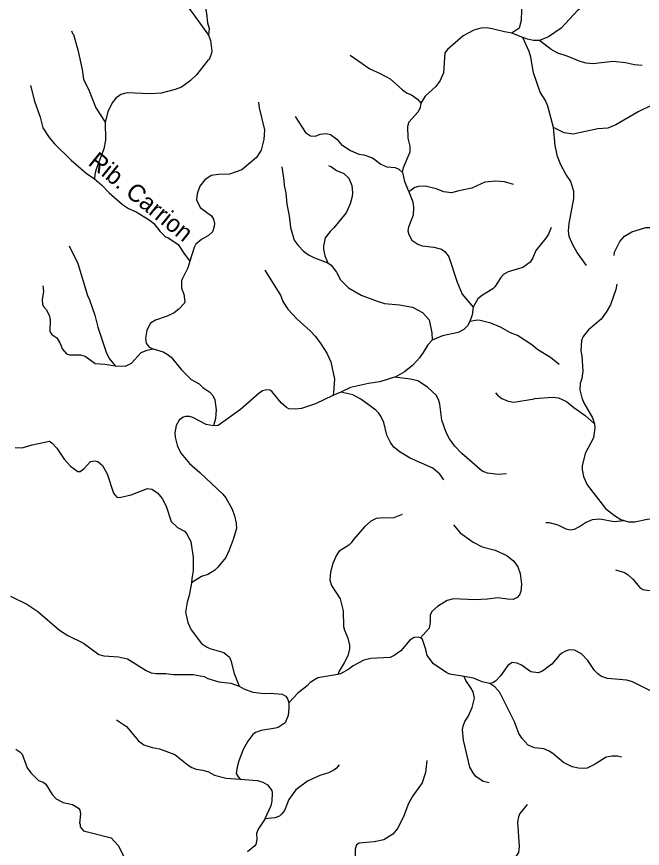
# Model space of a CAD drawing. Extents: x 500 to 555.2, y 9115.7 to 9171.
# Drawn here: x 528.19 to 533.92, y 9135.74 to 9143.36 of the extents above; entities that cross this region are included whole.
import ezdxf
from ezdxf.enums import TextEntityAlignment as Align

# ---------------------------------------------------------------- set-up
doc = ezdxf.new("R2010")
doc.units = 0
doc.header["$LTSCALE"] = 0.064
doc.layers.add('61', color=7, linetype='Continuous')
doc.layers.add('7', color=7, linetype='Continuous', lineweight=25)

msp = doc.modelspace()

# ---------------------------------------------------------------- linework, layer by layer
at = {"layer": '7'}
for p, q in [((532.8274, 9143.166), (532.7257, 9143.206)), ((531.1589, 9139.9191), (531.0875, 9139.8862)), ((529.994, 9139.6086), (529.9264, 9139.6229))]:
    msp.add_line(p, q, dxfattribs=at)
for points in [[(534.4742, 9144.2769), (534.4899, 9144.1646), (534.4965, 9144.0334), (534.4933, 9143.901), (534.47, 9143.7899), (534.4343, 9143.7344), (534.3943, 9143.7005), (534.3525, 9143.6763), (534.285, 9143.654), (534.2036, 9143.6426), (534.033, 9143.6473), (533.892, 9143.6442), (533.8193, 9143.6342), (533.7832, 9143.6211), (533.6414, 9143.5438), (533.5779, 9143.5183), (533.4747, 9143.4899), (533.4053, 9143.4646), (533.3305, 9143.4144), (533.1782, 9143.2495), (533.0607, 9143.1715), (532.98, 9143.1378)], [(529.6091, 9143.9899), (529.673, 9143.9438), (529.7397, 9143.8835), (529.7731, 9143.8379), (529.7821, 9143.8357), (529.8267, 9143.7671), (529.8362, 9143.7299), (529.8367, 9143.6871), (529.8482, 9143.6287), (529.907, 9143.5014), (529.9293, 9143.3848), (529.9386, 9143.3001), (529.953, 9143.2461), (529.9483, 9143.1857)], [(529.0863, 9143.8755), (529.1033, 9143.8572), (529.1147, 9143.8539), (529.3079, 9143.7173), (529.6741, 9143.5276), (529.7315, 9143.48), (529.7906, 9143.4062), (529.9483, 9143.1857)], [(532.8407, 9143.7046), (532.8388, 9143.7026), (532.8215, 9143.6515), (532.8072, 9143.5079), (532.8138, 9143.4193), (532.8119, 9143.321), (532.7918, 9143.2518), (532.7257, 9143.206)], [(528.6933, 9143.2275), (528.7016, 9143.2013), (528.7112, 9143.1911), (528.751, 9143.0507), (528.7898, 9142.8728), (528.803, 9142.7823), (528.8556, 9142.6779), (528.9151, 9142.52), (529.0012, 9142.3893)], [(532.7257, 9143.206), (532.6581, 9143.2167), (532.558, 9143.2425), (532.4978, 9143.2522), (532.442, 9143.2505), (532.3784, 9143.2337), (532.2812, 9143.1802), (532.1367, 9143.0557), (532.1137, 9143.0261), (532.0987, 9142.8402), (532.0703, 9142.7726), (532.0284, 9142.7178), (531.9313, 9142.627), (531.893, 9142.563)], [(529.9483, 9143.1857), (529.9486, 9143.1853), (529.9676, 9143.138), (529.9775, 9143.0407), (529.9739, 9143.0112), (529.9557, 9142.9631), (529.9404, 9142.9506), (529.8378, 9142.8219), (529.7797, 9142.7672), (529.7007, 9142.7118), (529.643, 9142.6894), (529.5145, 9142.6566), (529.4151, 9142.6486), (529.2028, 9142.6597), (529.1451, 9142.642), (529.0996, 9142.6112), (529.0657, 9142.5664), (529.0267, 9142.4852), (529.0012, 9142.3893)], [(533.1083, 9142.3399), (533.1081, 9142.3422), (533.055, 9142.5363), (533.0353, 9142.5888), (532.9857, 9142.6655), (532.9239, 9142.8404), (532.8995, 9142.9839), (532.8858, 9143.0355), (532.8274, 9143.166)], [(532.98, 9143.1378), (532.9781, 9143.137), (532.925, 9143.1382), (532.8691, 9143.1496), (532.8274, 9143.166)], [(533.9193, 9142.9099), (533.8482, 9142.9143), (533.7655, 9142.9323), (533.6532, 9142.9452), (533.4671, 9142.9225), (533.4053, 9142.9291), (533.3506, 9142.9458), (533.2341, 9142.9943), (533.1468, 9143.0208), (533.0869, 9143.0562), (532.98, 9143.1378)], [(531.2464, 9143.0027), (531.4259, 9142.8775), (531.5206, 9142.8365), (531.6113, 9142.7861), (531.7241, 9142.6872), (531.7683, 9142.657), (531.8062, 9142.6394), (531.8611, 9142.6002), (531.893, 9142.563)], [(528.3195, 9142.7268), (528.356, 9142.5809), (528.4055, 9142.4372), (528.4325, 9142.3369), (528.4879, 9142.2488), (528.5384, 9142.1914), (528.6897, 9142.0415), (528.8273, 9141.9239), (528.9056, 9141.8726)], [(530.4068, 9142.572), (530.4128, 9142.5198), (530.4615, 9142.3204), (530.4563, 9142.2306), (530.4302, 9142.1336), (530.3873, 9142.0674), (530.2533, 9141.9522), (530.14, 9141.9149), (530.0406, 9141.9119), (529.9738, 9141.9017), (529.9137, 9141.861), (529.8679, 9141.805), (529.8433, 9141.7338), (529.8388, 9141.6804), (529.8727, 9141.6087), (529.9742, 9141.533), (529.9937, 9141.5007), (530.0021, 9141.4627), (529.9987, 9141.434), (529.9833, 9141.3857), (529.948, 9141.3527), (529.8826, 9141.3165), (529.833, 9141.2716), (529.8183, 9141.2421), (529.776, 9141.1162)], [(531.893, 9142.563), (531.8917, 9142.5609), (531.8866, 9142.5235), (531.8692, 9142.4851), (531.7818, 9142.3902), (531.7691, 9142.3506), (531.7735, 9142.2432), (531.7917, 9142.1695), (531.7933, 9142.116), (531.7295, 9141.971), (531.7231, 9141.9323), (531.7236, 9141.9301)], [(534.0073, 9142.547), (533.8838, 9142.4855), (533.6785, 9142.3649), (533.6038, 9142.3354), (533.5134, 9142.3284), (533.287, 9142.2811), (533.2063, 9142.2924), (533.1083, 9142.3399)], [(529.0012, 9142.3893), (529.0047, 9142.2246), (528.9882, 9142.1459), (528.9152, 9141.9513), (528.9066, 9141.9103), (528.9056, 9141.8726)], [(530.7413, 9142.4414), (530.8373, 9142.2957), (530.881, 9142.2645), (530.9284, 9142.2629), (530.9697, 9142.2795), (531.0268, 9142.2874), (531.0662, 9142.2779), (531.123, 9142.233), (531.1701, 9142.1781), (531.1785, 9142.1771), (531.2494, 9142.1298), (531.3247, 9142.0977), (531.3719, 9142.0907), (531.4506, 9142.0628), (531.5261, 9142.005), (531.5799, 9141.9809), (531.6579, 9141.9764), (531.6914, 9141.9589), (531.7236, 9141.9301)], [(533.4105, 9141.0772), (533.3236, 9141.1957), (533.2878, 9141.2608), (533.2519, 9141.3422), (533.245, 9141.3962), (533.2501, 9141.4635), (533.2942, 9141.6911), (533.2942, 9141.7555), (533.2649, 9141.8458), (533.2192, 9141.9147), (533.174, 9141.9984), (533.1441, 9142.0754), (533.122, 9142.1767), (533.1083, 9142.3399)], [(531.0478, 9141.9925), (531.0745, 9141.9815), (531.1214, 9141.9487), (531.1871, 9141.9191), (531.2327, 9141.8775), (531.2616, 9141.8098), (531.2683, 9141.7437), (531.2652, 9141.711), (531.2468, 9141.6434), (531.2075, 9141.5589), (531.0956, 9141.4228), (531.0619, 9141.3903), (531.0174, 9141.3306), (531.0013, 9141.2555), (531.002, 9141.2264), (531.0143, 9141.1672), (531.0415, 9141.1029)], [(530.6196, 9141.982), (530.6387, 9141.8572), (530.6406, 9141.8106), (530.6551, 9141.7417), (530.665, 9141.6383), (530.6859, 9141.531), (530.6995, 9141.4242), (530.7339, 9141.31), (530.7679, 9141.2612), (530.8175, 9141.2083), (530.8629, 9141.1765), (530.9186, 9141.1478), (531.0415, 9141.1029)], [(531.7236, 9141.9301), (531.7429, 9141.8473), (531.7837, 9141.7516)], [(528.9056, 9141.8726), (528.9682, 9141.8175), (529.0374, 9141.7434), (529.1602, 9141.6352), (529.2168, 9141.6005), (529.2848, 9141.5679), (529.4145, 9141.4891), (529.4466, 9141.462), (529.5032, 9141.3935), (529.5556, 9141.3417), (529.5761, 9141.3341), (529.6708, 9141.2706), (529.7272, 9141.1814), (529.776, 9141.1162)], [(532.7404, 9141.819), (532.6599, 9141.8448), (532.5804, 9141.8511), (532.4795, 9141.8393), (532.3599, 9141.7859), (532.2419, 9141.7627), (532.174, 9141.743), (532.1022, 9141.7524), (532.034, 9141.7809), (531.9361, 9141.8037), (531.8713, 9141.8004), (531.8378, 9141.7922), (531.7837, 9141.7516)], [(531.7837, 9141.7516), (531.8179, 9141.6619), (531.8245, 9141.6085), (531.8212, 9141.5397), (531.7784, 9141.4298), (531.7739, 9141.3953), (531.782, 9141.3625), (531.8095, 9141.3105), (531.8666, 9141.2742), (531.904, 9141.259), (532.0116, 9141.246), (532.083, 9141.228), (532.1149, 9141.2017), (532.1489, 9141.1583), (532.2259, 9140.9243), (532.2718, 9140.8161), (532.3712, 9140.6957)], [(533.6627, 9141.1679), (533.6658, 9141.2013), (533.7145, 9141.2983), (533.7569, 9141.3475), (533.8242, 9141.3869), (533.9543, 9141.4264), (534.0029, 9141.4265), (534.1613, 9141.4446), (534.2637, 9141.4821), (534.3414, 9141.5035), (534.5043, 9141.5199), (534.6085, 9141.5154)], [(533.0854, 9141.4261), (533.0613, 9141.3658), (533.0387, 9141.3268), (532.9451, 9141.216), (532.9173, 9141.1465), (532.895, 9141.1079), (532.8278, 9141.0588), (532.6929, 9141.0198), (532.649, 9140.9942), (532.6238, 9140.9676), (532.5709, 9140.8819), (532.5522, 9140.8631), (532.4572, 9140.8077), (532.4147, 9140.7732), (532.3712, 9140.6957)], [(528.6735, 9141.2564), (528.7509, 9141.0961), (528.8391, 9140.8021), (528.8589, 9140.7621), (528.908, 9140.6226), (528.9344, 9140.5135), (529.0107, 9140.2844), (529.0378, 9140.2274), (529.0941, 9140.1587)], [(529.776, 9141.1162), (529.7581, 9141.0573), (529.7022, 9140.9391), (529.7022, 9140.8688), (529.7235, 9140.814), (529.7301, 9140.7445), (529.7249, 9140.731), (529.6774, 9140.6769), (529.6339, 9140.6432), (529.5702, 9140.6126), (529.462, 9140.578), (529.4157, 9140.5506), (529.3842, 9140.4871), (529.3708, 9140.4137), (529.3768, 9140.3654), (529.4058, 9140.3302), (529.4391, 9140.3154)], [(531.0415, 9141.1029), (531.0715, 9141.0802), (531.1216, 9141.0161), (531.158, 9140.9479), (531.2308, 9140.8727), (531.3476, 9140.8072), (531.5005, 9140.7471), (531.561, 9140.7303), (531.6981, 9140.7176), (531.8174, 9140.6949), (531.9066, 9140.6472), (531.9689, 9140.5793), (531.9945, 9140.4615), (531.9952, 9140.3958)], [(530.4633, 9141.0353), (530.61, 9140.7994), (530.6303, 9140.7496), (530.676, 9140.6789), (530.7587, 9140.5862), (530.8798, 9140.4799), (530.9273, 9140.429), (530.9782, 9140.3619), (531.0323, 9140.2766), (531.0669, 9140.1972), (531.1012, 9140.0371), (531.0943, 9139.9117), (531.0875, 9139.8862)], [(528.4297, 9140.892), (528.4374, 9140.8442), (528.4243, 9140.7648), (528.4273, 9140.7245), (528.4369, 9140.7024), (528.4629, 9140.6738), (528.4902, 9140.6232), (528.498, 9140.5849), (528.4951, 9140.4751), (528.5143, 9140.4475), (528.5581, 9140.4146), (528.5863, 9140.3689), (528.6113, 9140.3127), (528.6464, 9140.2699), (528.6759, 9140.2587), (528.7763, 9140.2585), (528.8193, 9140.2477), (528.911, 9140.1801), (529.0007, 9140.1731), (529.0941, 9140.1587)], [(533.6864, 9140.9057), (533.6779, 9140.8567), (533.6302, 9140.7189), (533.5912, 9140.6506), (533.5428, 9140.5874), (533.4289, 9140.4882), (533.3781, 9140.4272), (533.3647, 9140.3903), (533.3582, 9140.2969), (533.3664, 9140.2497), (533.3762, 9140.1119), (533.3664, 9140.0437), (533.3531, 9139.9963), (533.3485, 9139.9398), (533.3657, 9139.8678), (533.3855, 9139.822), (533.4641, 9139.6823), (533.4818, 9139.6286)], [(532.3712, 9140.6957), (532.3629, 9140.6258), (532.3418, 9140.5655)], [(532.3418, 9140.5655), (532.321, 9140.5256), (532.2872, 9140.4915), (532.235, 9140.4659), (532.091, 9140.4342), (531.9952, 9140.3958)], [(533.1581, 9140.1726), (533.0789, 9140.2343), (532.9652, 9140.3052), (532.9104, 9140.352), (532.7764, 9140.4385), (532.7139, 9140.4618), (532.6217, 9140.5144), (532.5327, 9140.549), (532.4354, 9140.5749), (532.4111, 9140.5767), (532.3418, 9140.5655)], [(531.9952, 9140.3958), (531.9581, 9140.3522), (531.9126, 9140.2813), (531.8803, 9140.234), (531.8167, 9140.1638), (531.743, 9140.1047), (531.6561, 9140.0552), (531.6525, 9140.0541)], [(529.0941, 9140.1587), (529.0986, 9140.158), (529.187, 9140.1555), (529.2437, 9140.1824), (529.3305, 9140.2801), (529.3851, 9140.3042), (529.4391, 9140.3154)], [(529.4391, 9140.3154), (529.4413, 9140.3144), (529.5332, 9140.287), (529.5708, 9140.2667), (529.6057, 9140.2383), (529.7, 9140.1213), (529.7907, 9140.0355), (529.8615, 9139.9936), (529.8962, 9139.9613), (529.9588, 9139.9192), (529.988, 9139.889), (530.0073, 9139.8486), (530.0169, 9139.7565), (530.0111, 9139.6758), (529.994, 9139.6086)], [(531.6525, 9140.0541), (531.5169, 9140.0127), (531.4118, 9139.9988), (531.2487, 9139.9605), (531.1589, 9139.9191)], [(532.6781, 9139.1699), (532.6016, 9139.1646), (532.5038, 9139.1776), (532.4547, 9139.1959), (532.2665, 9139.3573), (532.2046, 9139.4233), (532.1537, 9139.4904), (532.1244, 9139.5478), (532.084, 9139.6609), (532.0676, 9139.8093), (532.0585, 9139.8417), (532.0361, 9139.8862), (531.9529, 9139.9642), (531.8666, 9140.0208), (531.7979, 9140.0381), (531.6525, 9140.0541)], [(531.0875, 9139.8862), (530.9283, 9139.8128), (530.7995, 9139.7695), (530.7425, 9139.7622), (530.685, 9139.7655), (530.6622, 9139.7785), (530.6148, 9139.8198), (530.5302, 9139.9222), (530.5116, 9139.9369), (530.4795, 9139.9385), (530.4436, 9139.9303), (530.4136, 9139.9106), (530.2423, 9139.7585), (530.0375, 9139.6146), (529.994, 9139.6086)], [(532.1021, 9139.1143), (532.0673, 9139.1677), (532.0036, 9139.2222), (531.7953, 9139.3154), (531.7021, 9139.3675), (531.6462, 9139.415), (531.6144, 9139.457), (531.5807, 9139.5242), (531.5525, 9139.6394), (531.5266, 9139.6979), (531.5051, 9139.7282), (531.4797, 9139.7523), (531.3418, 9139.8537), (531.2712, 9139.8937), (531.1589, 9139.9191)], [(532.5759, 9139.9123), (532.5953, 9139.8901), (532.6347, 9139.8616), (532.6913, 9139.8368), (532.7431, 9139.8276), (532.9295, 9139.8566), (532.9368, 9139.8615), (533.0994, 9139.8729), (533.1544, 9139.8661), (533.2266, 9139.834), (533.2941, 9139.7768), (533.398, 9139.7038), (533.4818, 9139.6286)], [(529.9264, 9139.6229), (529.8037, 9139.6877), (529.7736, 9139.6959), (529.7365, 9139.696), (529.7158, 9139.6895), (529.678, 9139.6617), (529.6518, 9139.6119), (529.64, 9139.5445), (529.6433, 9139.5075), (529.6644, 9139.4204), (529.6975, 9139.3575), (529.7747, 9139.2656), (529.8699, 9139.1836), (530.0782, 9138.9835), (530.1062, 9138.9508), (530.1636, 9138.8481), (530.1861, 9138.7866), (530.2008, 9138.7201), (530.2038, 9138.6698), (530.1745, 9138.5681), (530.1377, 9138.4708), (530.1067, 9138.4061), (530.0336, 9138.3153), (530.0022, 9138.2853), (529.9424, 9138.2497), (529.8845, 9138.2319), (529.793, 9138.1717)], [(533.4818, 9139.6286), (533.4874, 9139.5908), (533.4751, 9139.5007), (533.3966, 9139.3562), (533.3711, 9139.2438), (533.3685, 9139.211), (533.3811, 9139.1455), (533.415, 9139.0713), (533.5843, 9138.8532), (533.6651, 9138.7889), (533.7226, 9138.7537), (533.7538, 9138.7445)], [(528.1776, 9139.4132), (528.2428, 9139.409), (528.334, 9139.4367), (528.4489, 9139.4605), (528.491, 9139.4711), (528.5148, 9139.4539), (528.5584, 9139.406), (528.6276, 9139.3045), (528.6831, 9139.2404), (528.7527, 9139.1931), (528.7741, 9139.1928), (528.8109, 9139.2199), (528.8661, 9139.2827), (528.911, 9139.2908), (528.9356, 9139.2832), (528.9772, 9139.2473), (529.0189, 9139.1691), (529.0794, 9138.9931), (529.1089, 9138.9561), (529.1317, 9138.9531), (529.2402, 9138.9793), (529.3898, 9139.0363), (529.4291, 9139.0316), (529.4806, 9138.9971), (529.5245, 9138.9435), (529.5596, 9138.8752), (529.6053, 9138.7354), (529.663, 9138.6808), (529.727, 9138.6453), (529.7464, 9138.6259), (529.787, 9138.5516), (529.8087, 9138.4034), (529.8069, 9138.2853), (529.7958, 9138.2131), (529.793, 9138.1717)], [(531.7214, 9138.7972), (531.6454, 9138.7673), (531.5162, 9138.7658), (531.4835, 9138.7608), (531.4343, 9138.7363), (531.3759, 9138.6862), (531.2753, 9138.569), (531.2554, 9138.5383), (531.2326, 9138.5172), (531.1431, 9138.4581), (531.1209, 9138.4247), (531.0867, 9138.349), (531.0649, 9138.2706), (531.0606, 9138.1985), (531.0732, 9138.1497), (531.1534, 9138.0267), (531.1815, 9137.9178), (531.185, 9137.7729), (531.193, 9137.7381), (531.2247, 9137.6671), (531.2405, 9137.6029), (531.2389, 9137.5695), (531.2226, 9137.5045), (531.1906, 9137.4403), (531.1433, 9137.3645), (531.132, 9137.3344)], [(533.0386, 9138.7245), (533.0674, 9138.7245), (533.1467, 9138.705), (533.2189, 9138.6671), (533.2637, 9138.6594), (533.2988, 9138.6647), (533.3462, 9138.687), (533.4012, 9138.7242), (533.4655, 9138.7527), (533.5308, 9138.7576), (533.6638, 9138.7331), (533.7538, 9138.7445)], [(533.7538, 9138.7445), (533.7944, 9138.7326), (533.8511, 9138.7326), (533.9642, 9138.7561), (534.0667, 9138.7585), (534.1341, 9138.7445), (534.2418, 9138.7005), (534.348, 9138.6459), (534.4158, 9138.6247), (534.478, 9138.6249), (534.5321, 9138.6401)], [(532.1925, 9138.7036), (532.2529, 9138.6295), (532.3709, 9138.546), (532.4548, 9138.5012), (532.5738, 9138.4703), (532.6797, 9138.4244), (532.7428, 9138.3726), (532.7808, 9138.3197), (532.8007, 9138.2582), (532.8137, 9138.1606), (532.8082, 9138.0936), (532.7972, 9138.0642), (532.7746, 9138.038), (532.7392, 9138.0196), (532.685, 9138.0223), (532.5987, 9138.036), (532.5031, 9138.0228), (532.3871, 9138.018), (532.1914, 9138.0259), (532.1325, 9138.011), (532.0439, 9137.9568), (531.9933, 9137.9106), (531.9788, 9137.8779), (531.977, 9137.8113), (531.9686, 9137.7567), (531.8898, 9137.6698)], [(533.6766, 9138.2922), (533.7562, 9138.2674), (533.7923, 9138.2445), (533.8332, 9138.2055), (533.8985, 9138.1289), (533.9262, 9138.1103), (533.9799, 9138.1033), (534.032, 9138.1157), (534.0805, 9138.1385), (534.1641, 9138.1987), (534.1976, 9138.2594), (534.2179, 9138.318), (534.2569, 9138.3667), (534.3184, 9138.4017), (534.4437, 9138.4384), (534.4803, 9138.4608), (534.4969, 9138.4794), (534.5162, 9138.5166), (534.5321, 9138.6401)], [(529.793, 9138.1717), (529.7715, 9138.0582), (529.7528, 9137.996), (529.7384, 9137.9042), (529.7575, 9137.8111), (529.7886, 9137.7417), (529.8844, 9137.6176), (529.9285, 9137.5865), (529.9598, 9137.5724), (530.0882, 9137.5349), (530.1394, 9137.4917), (530.1533, 9137.4612), (530.1846, 9137.3431), (530.2293, 9137.2264)], [(528.134, 9138.0509), (528.2843, 9137.9771), (528.3842, 9137.9103), (528.5839, 9137.7387), (528.6611, 9137.6905), (528.8031, 9137.6209), (528.9447, 9137.5157), (528.9889, 9137.5046), (529.1253, 9137.4945), (529.2072, 9137.4785), (529.3768, 9137.3703), (529.4221, 9137.3501), (529.4679, 9137.3422), (529.5563, 9137.3435), (529.6266, 9137.3339), (529.8077, 9137.3337), (529.908, 9137.3143), (529.943, 9137.2957), (530.0433, 9137.2667), (530.1521, 9137.2549), (530.2293, 9137.2264)], [(531.8898, 9137.6698), (531.8894, 9137.6702), (531.8668, 9137.6758), (531.8305, 9137.6713), (531.7932, 9137.6465), (531.7081, 9137.5505), (531.648, 9137.5065), (531.6128, 9137.4904), (531.4349, 9137.4799), (531.3701, 9137.4655), (531.2716, 9137.4134), (531.2331, 9137.3835), (531.1575, 9137.3386), (531.132, 9137.3344)], [(532.289, 9137.3146), (532.1586, 9137.3374), (532.1292, 9137.349), (532.0088, 9137.4302), (531.9496, 9137.5089), (531.939, 9137.5616), (531.9074, 9137.654), (531.8898, 9137.6698)], [(534.0455, 9137.1583), (533.8321, 9137.2661), (533.7792, 9137.2815), (533.6034, 9137.296), (533.5458, 9137.3156), (533.512, 9137.3393), (533.4823, 9137.3689), (533.421, 9137.4613), (533.3653, 9137.522), (533.2994, 9137.5556), (533.255, 9137.56), (533.2185, 9137.5484), (533.1829, 9137.529), (533.1593, 9137.5089), (533.093, 9137.428), (533.0062, 9137.3654), (532.9656, 9137.3503), (532.8995, 9137.3585), (532.8131, 9137.4178), (532.7745, 9137.436), (532.7289, 9137.4448), (532.6896, 9137.4163), (532.6234, 9137.3208), (532.5775, 9137.273), (532.5505, 9137.2574), (532.5234, 9137.2504)], [(531.132, 9137.3344), (530.9482, 9137.3039), (530.8804, 9137.2605), (530.8519, 9137.2306), (530.7651, 9137.1633), (530.684, 9137.0754)], [(532.5174, 9136.343), (532.4642, 9136.355), (532.3971, 9136.4006), (532.3712, 9136.4329), (532.3403, 9136.4864), (532.2839, 9136.7309), (532.2741, 9136.8287), (532.2791, 9136.8615), (532.2953, 9136.9019), (532.3252, 9136.949), (532.3616, 9137.0322), (532.3853, 9137.1172), (532.3708, 9137.1748), (532.3511, 9137.2125), (532.3047, 9137.2775), (532.289, 9137.3146)], [(532.5234, 9137.2504), (532.5225, 9137.2509), (532.4529, 9137.2669), (532.375, 9137.2995), (532.289, 9137.3146)], [(530.2293, 9137.2264), (530.2716, 9137.2024), (530.355, 9137.1732), (530.4593, 9137.1601), (530.5138, 9137.1617), (530.6212, 9137.1537), (530.6551, 9137.1362), (530.6758, 9137.1052), (530.684, 9137.0754)], [(533.7295, 9136.5783), (533.6925, 9136.5856), (533.6444, 9136.586), (533.5902, 9136.5778), (533.4883, 9136.5115), (533.4156, 9136.4773), (533.3751, 9136.4718), (533.3349, 9136.4775), (533.2771, 9136.4887), (533.1982, 9136.5277), (533.1018, 9136.6113), (533.0679, 9136.6318), (533.0175, 9136.6518), (532.9328, 9136.6632), (532.8767, 9136.6858), (532.819, 9136.7472), (532.7901, 9136.7938), (532.7512, 9136.9008), (532.6152, 9137.1698), (532.5709, 9137.2207), (532.5234, 9137.2504)], [(530.684, 9137.0754), (530.6833, 9137.0245), (530.6779, 9136.9584), (530.6491, 9136.8918), (530.5848, 9136.8496), (530.5616, 9136.8419), (530.4304, 9136.8221), (530.3792, 9136.8014), (530.355, 9136.7844), (530.3077, 9136.7243), (530.2666, 9136.6456), (530.2265, 9136.5439), (530.2103, 9136.4861), (530.2026, 9136.4274), (530.2198, 9136.396), (530.2389, 9136.3766), (530.2396, 9136.3765)], [(529.1047, 9136.9185), (529.1961, 9136.8574), (529.3071, 9136.7266), (529.3571, 9136.6895), (529.4318, 9136.665), (529.4982, 9136.6533), (529.6413, 9136.6007), (529.7615, 9136.5048), (529.797, 9136.4826), (529.8363, 9136.4675), (529.895, 9136.458), (529.9492, 9136.4416), (530.0031, 9136.4114), (530.11, 9136.3842), (530.2396, 9136.3765)], [(528.1843, 9136.6492), (528.2214, 9136.6244), (528.2417, 9136.6028), (528.2863, 9136.4783), (528.32, 9136.4335), (528.3903, 9136.3647), (528.4351, 9136.3467), (528.4589, 9136.3281), (528.5174, 9136.2338), (528.5545, 9136.1964), (528.6161, 9136.1633), (528.7015, 9136.1447), (528.7584, 9136.1106), (528.7687, 9136.0904), (528.7751, 9136.0566), (528.7672, 9135.9682), (528.7719, 9135.9653), (528.7744, 9135.9385), (528.8036, 9135.9021), (529.0563, 9135.8397), (529.1201, 9135.7686), (529.1821, 9135.6478), (529.2558, 9135.5426), (529.2768, 9135.4849)], [(531.947, 9136.5478), (531.9359, 9136.4378), (531.9053, 9136.3412), (531.8204, 9136.223), (531.7797, 9136.1515), (531.7372, 9136.0394), (531.6828, 9135.9271), (531.6365, 9135.873), (531.5539, 9135.82), (531.4648, 9135.8019), (531.327, 9135.7898), (531.3024, 9135.7747), (531.29, 9135.7337), (531.2915, 9135.6084), (531.2695, 9135.4791), (531.2436, 9135.4208), (531.2048, 9135.3661), (531.1729, 9135.3324), (531.1171, 9135.2966)], [(531.1436, 9136.5058), (531.121, 9136.4766), (531.0963, 9136.458), (531.0477, 9136.4336), (530.9663, 9136.4076), (530.8536, 9136.3562), (530.7482, 9136.2786), (530.6834, 9136.1896), (530.6432, 9136.09), (530.6202, 9136.057), (530.5971, 9136.0364), (530.5544, 9136.0216), (530.4641, 9136.0116)], [(530.2396, 9136.3765), (530.3979, 9136.3632), (530.4457, 9136.3466), (530.4894, 9136.3234), (530.5279, 9136.2706), (530.532, 9136.2513), (530.5288, 9136.1733), (530.5202, 9136.1326), (530.4641, 9136.0116)], [(532.8661, 9136.1438), (532.8006, 9136.0626), (532.7865, 9136.0304), (532.7793, 9135.9829), (532.7923, 9135.7592), (532.7858, 9135.7051), (532.7468, 9135.6467), (532.6999, 9135.6225), (532.656, 9135.5634), (532.6284, 9135.4935), (532.612, 9135.4246), (532.6071, 9135.3781), (532.6204, 9135.2668), (532.6234, 9135.1557), (532.6085, 9135.0867), (532.5845, 9135.0403)], [(530.4641, 9136.0116), (530.4626, 9136.0083), (530.4019, 9135.9185), (530.3878, 9135.8788), (530.3908, 9135.8216), (530.381, 9135.7779), (530.3724, 9135.764), (530.3046, 9135.7095)]]:
    msp.add_lwpolyline(points, dxfattribs=at)

# ---------------------------------------------------------------- texts
at = {"layer": '61'}
msp.add_text('Rib. Carrion', height=0.16, rotation=320.906, dxfattribs=at).set_placement((529.28, 9141.6457), align=Align.CENTER)

doc.saveas('drawing.dxf')
